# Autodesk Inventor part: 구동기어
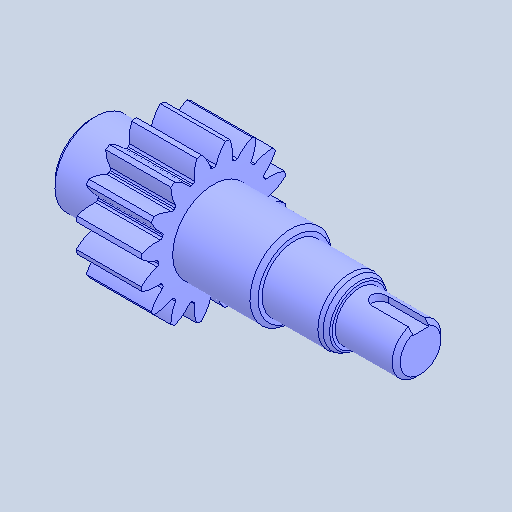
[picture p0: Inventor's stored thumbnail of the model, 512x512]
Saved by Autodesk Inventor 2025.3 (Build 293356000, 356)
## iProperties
Created: 2025-10
Part Number: 구동기어
Material: 강철, 합금
Document SubType Name: Modeling
Designer: PC-15
Density: 7.73 g/cm^3
Appearance: 기본값
Author: jhkim
Sending System: Autodesk Inventor 2026
Preprocessor: ST-DEVELOPER v20.1
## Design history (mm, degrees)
feature "솔리드1"
node "솔리드2"
